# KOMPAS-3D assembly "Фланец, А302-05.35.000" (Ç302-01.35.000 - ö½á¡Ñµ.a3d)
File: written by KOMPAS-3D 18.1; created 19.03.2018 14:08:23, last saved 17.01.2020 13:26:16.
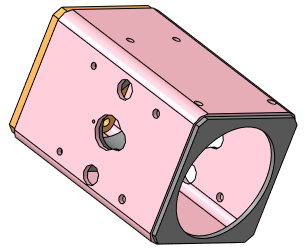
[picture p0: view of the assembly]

Document properties: Автор: Милов; Полное имя файла: D:\Мембранные насосы\Мембранный электропривод\А302-00.00.000 - ASTRA-302 (МЭ200)\3Д ПВХ\А302-01.35.000 - Фланец.a3d

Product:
- Part/product: Фланец  | designation А302-05.35.000  | pos. 0
    Масса: 15.1675
    Раздел спецификации: Сборочные единицы
    Форматы листов документа: 2xA3
    Примечание: @100~)2xA3
    source file: ..\А302-04.00.000 - Мембранный насос ASTRA-302-PP Чертежи\А302-04.35.000 - Фланец.cdw
  - Component [detail]: FB 063  | pos. 11  | Масса: 1.71461; Раздел спецификации: Детали; source file: FB 063 .m3d
  - Component [detail]: Опора подшиника  | designation А302-05.35.003  | pos. 7  | Масса: 10.2382; Раздел спецификации: Детали
  - Component [detail]: Труба 140х140х6  | designation А302-05.35.001  | pos. 1  | Масса: 2.81713; Раздел спецификации: Детали; Форматы листов документа: A4; Примечание: Заим.
  - Component [detail]: Пластина  | designation А302-05.35.002  | pos. 2  | Масса: 0.658749; Раздел спецификации: Детали; Форматы листов документа: A4; Примечание: Заим.
- Part/product: Фланец  | designation А302-04.35.000  | pos. 0
    Масса: 8.08129
    Раздел спецификации: Сборочные единицы
    Форматы листов документа: 2xA3
    Примечание: @100~)2xA3
    source file: ..\А302-04.00.000 - Мембранный насос ASTRA-302-PP Чертежи\А302-04.35.000 - Фланец.cdw, ..\А302-04.00.000 - Мембранный насос ASTRA-302-PP\А302-04.35.000 - Фланец.cdw
  - Component [detail]: Стенка  | designation А302-04.35.004  | pos. 12  | Масса: 0.256038; Раздел спецификации: Детали; source file: А302-04.35.004 - Стенка.m3d
  - Component [detail]: Пластина  | designation А302-04.35.002  | pos. 2  | Масса: 1.18936; Раздел спецификации: Детали; Форматы листов документа: A4; Примечание: Заим.
  - Component [detail]: Труба 140х140х6  | designation А302-04.35.001  | pos. 1  | Масса: 4.48359; Раздел спецификации: Детали; Форматы листов документа: A4; Примечание: Заим.
  - Component [detail]: Опора подшипника  | designation А302-04.35.003  | pos. 7  | Масса: 2.1523; Раздел спецификации: Детали; source file: А302-04.35.003 - Опора подшиника.m3d
- Part/product: Фланец  | designation А302-01.35.000  | pos. 0
    Масса: 8.26617
    Раздел спецификации: Сборочные единицы
    Форматы листов документа: 2xA3
    Примечание: @100~)2xA3
    source file: А302-01.35.000 - Фланец.cdw
  - Component [detail]: Труба 140х140х4  | designation А302-00.35.001  | pos. 1  | Масса: 4.39548; Раздел спецификации: Детали; Форматы листов документа: A4; Примечание: Заим.; source file: ..\3Д\А302-00.35.001 - Труба 140х140х4.m3d
  - Component [detail]: Пластина  | designation А302-00.35.002  | pos. 2  | Масса: 0.697075; Раздел спецификации: Детали; Форматы листов документа: A4; Примечание: Заим.; source file: ..\3Д\А302-00.35.002 - Пластина.m3d

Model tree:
1. Эскиз:1  (with: Операция выдавливания:3)
2. Вырезать элемент выдавливания:1
     Расстояние 2 = 265
3. Эскиз:2  (with: Операция выдавливания:1)
4. Вырезать элемент выдавливания:2
     Расстояние 1 = 270
5. Эскиз:3  (with: Операция выдавливания:3)
6. Вырезать элемент выдавливания:3
     Расстояние 1 = 137
7. Эскиз:4  (with: Вырезать элемент выдавливания:3)
8. Вырезать элемент выдавливания:4
     Расстояние 1 = 269
9. Эскиз:5  (with: Вырезать элемент выдавливания:3, Вырезать элемент выдавливания:4)
10. Вырезать элемент выдавливания:5
     Расстояние 1 = 10
11. Массив по концентрической сетке:1  (with: Вырезать элемент выдавливания:5, Эскиз:5, Вырезать элемент выдавливания:4)  (8 pattern instances)
     Шаг 2 = 360
12. Эскиз:6  (with: Вырезать элемент выдавливания:1, Вырезать элемент выдавливания:3)
13. Вырезать элемент выдавливания:6
     Расстояние 1 = 139.5
14. Эскиз:7  (with: Вырезать элемент выдавливания:1, Вырезать элемент выдавливания:6)
15. Вырезать элемент выдавливания:7
     Расстояние 1 = 139.5
16. Массив по концентрической сетке:2  (with: Вырезать элемент выдавливания:7, Эскиз:7, Вырезать элемент выдавливания:6)  (4 pattern instances)
     Шаг 2 = 360
17. Эскиз:8  (with: Вырезать элемент выдавливания:1, Вырезать элемент выдавливания:6, Вырезать элемент выдавливания:7)
18. Вырезать элемент выдавливания:8
     Расстояние 1 = 139.5
19. Массив по концентрической сетке:3  (with: Вырезать элемент выдавливания:8, Эскиз:8, Вырезать элемент выдавливания:6)  (2 pattern instances)
     Шаг 2 = 360
20. Эскиз:9  (with: Вырезать элемент выдавливания:2)
21. Вырезать элемент выдавливания:9
     Расстояние 1 = 7
22. Зеркальный массив:1
23. Экземпляр ( 1 )
24. Экземпляр ( 2 )  (with: Вырезать элемент выдавливания:9)
25. Эскиз:10  (with: Вырезать элемент выдавливания:1, Вырезать элемент выдавливания:6, Вырезать элемент выдавливания:7)
26. Вырезать элемент выдавливания:10
     Расстояние 1 = 139.5
27. Массив по концентрической сетке:4  (with: Вырезать элемент выдавливания:10, Эскиз:10, Вырезать элемент выдавливания:6)  (3 pattern instances)
     Шаг 2 = 180
28. Эскиз:11  (with: Операция выдавливания:1)
29. Вырезать элемент выдавливания:11
     Расстояние 1 = 10; На расстояние 1 = 8
30. Зеркальный массив:2  (with: Экземпляр ( 1 ), Экземпляр ( 2 ), Вырезать элемент выдавливания:11)
31. Эскиз:12  (with: Вырезать элемент выдавливания:1, Вырезать элемент выдавливания:6)
32. Вырезать элемент выдавливания:12
     Расстояние 1 = 139.5; На расстояние 1 = 8
33. Условное изображение резьбы:1  (with: Вырезать элемент выдавливания:12)  (labels: M4; cil0_24705-2004 coarse)
     Длина резьбы = 3.5; Шаг резьбы = 0.7; Номинальный диаметр резьбы = 4
34. Подгонка:1  (with: Вырезать элемент выдавливания:12)
35. Условное изображение резьбы:2  (with: Вырезать элемент выдавливания:12)  (labels: M4; cil0_24705-2004 coarse)
     Длина резьбы = 3.5; Шаг резьбы = 0.7; Номинальный диаметр резьбы = 4
36. Подгонка:2  (with: Вырезать элемент выдавливания:12)
37. Фаска:1  (with: Вырезать элемент выдавливания:12)
     Угол = 45; Длина 1 = 0.5; Длина 2 = 0.5
38. Эскиз:13  (with: Вырезать элемент выдавливания:2, Вырезать элемент выдавливания:11)
39. Элемент выдавливания:1  (with: Операция выдавливания:3, Операция выдавливания:1)
     Расстояние 2 = 10
40. Эскиз:14  (with: Операция выдавливания:1)
41. Элемент выдавливания:3
     Расстояние 1 = 133.5; Расстояние 2 = 5.5
42. Условное изображение резьбы:3  (with: Элемент выдавливания:3, Элемент выдавливания:12)  (labels: M8x1; cil0_24705-2004 fine)
     Длина резьбы = 10; Шаг резьбы = 1; Номинальный диаметр резьбы = 8
43. Подгонка:1  (with: Элемент выдавливания:3)
44. Условное изображение резьбы:4  (with: Элемент выдавливания:3, Элемент выдавливания:12)  (labels: M8x1; cil0_24705-2004 fine)
     Длина резьбы = 10; Шаг резьбы = 1; Номинальный диаметр резьбы = 8
45. Подгонка:2  (with: Элемент выдавливания:3)
46. Условное изображение резьбы:5  (with: Элемент выдавливания:3, Элемент выдавливания:12)  (labels: M8x1; cil0_24705-2004 fine)
     Длина резьбы = 10; Шаг резьбы = 1; Номинальный диаметр резьбы = 8
47. Подгонка:3  (with: Элемент выдавливания:3)
48. Условное изображение резьбы:6  (with: Элемент выдавливания:3, Элемент выдавливания:12)  (labels: M8x1; cil0_24705-2004 fine)
     Длина резьбы = 10; Шаг резьбы = 1; Номинальный диаметр резьбы = 8
49. Подгонка:4  (with: Элемент выдавливания:3)
50. Отверстие:6  (with: Элемент выдавливания:2)  (labels: M8x1)
     Глубина выреза = 30; Диаметр отверстия = 6.91747; Угол конуса дна = 118; Расстояние 1 = 107; Расстояние 2 = 64
51. M8x1  (with: Отверстие:6, Элемент выдавливания:2)  (labels: M8x1; cil0_24705-2004 fine)
     Длина резьбы = 20; Шаг резьбы = 1; Номинальный диаметр резьбы = 8
52. Отверстие:7  (with: Элемент выдавливания:2, M8x1)  (labels: M8x1; cil0_24705-2004 fine)
     Глубина выреза = 30; Диаметр отверстия = 6.91747; Угол конуса дна = 118; Расстояние 1 = 15; Расстояние 2 = 64; Длина резьбы = 20; Шаг резьбы = 1; Номинальный диаметр резьбы = 8
53. Зеркальный массив:3
54. Экземпляр ( 1 )
55. Экземпляр ( 2 )  (with: Отверстие:7)
56. Отверстие:6
57. Эскиз:16  (with: Операция выдавливания:1)
58. Элемент выдавливания:7
     Расстояние 1 = 10
59. Элемент выдавливания:8  (with: Элемент выдавливания:1)
     Расстояние 2 = 3
60. Точка:1  (with: Элемент выдавливания:7)
     X = 31.5; Y = -70; Z = 129.5
61. Точка:2  (with: Элемент выдавливания:7)
     X = -31.5; Y = -70; Z = 129.5
62. Отверстие:8  (with: Элемент выдавливания:1, Фаска:1, M8x1)  (labels: M8x1; cil0_24705-2004 fine)
     Глубина выреза = 15; Диаметр отверстия = 6.91747; Угол конуса дна = 118; Расстояние 1 = -85.5; Расстояние 2 = 12.5; Длина резьбы = 15; Шаг резьбы = 1; Номинальный диаметр резьбы = 8
63. Отверстие:9  (with: Элемент выдавливания:1, Фаска:1, M8x1, Операция выдавливания:3, Элемент выдавливания:8)  (labels: M8x1; cil0_24705-2004 fine)
     Глубина выреза = 15; Диаметр отверстия = 6.91747; Угол конуса дна = 118; Расстояние 1 = -22.5; Расстояние 2 = 12.5; Длина резьбы = 15; Шаг резьбы = 1; Номинальный диаметр резьбы = 8; Расстояние = 50; Ориентация = 2

Referenced files in D:\Мембранные насосы\Мембранный электропривод\А302-00.00.000 - ASTRA-302 (МЭ200)\3Д\: А302-00.35.002 - Пластина.m3d, А302-00.35.001 - Труба 140х140х4.m3d
Referenced files in D:\Мембранные насосы\Мембранный электропривод\А302-00.00.000 - ASTRA-302 (МЭ200)\3Д ПВХ\: А302-04.35.003 - Опора подшиника.m3d, FB 063 .m3d, А302-04.35.004 - Стенка.m3d, А302-01.35.000 - Фланец.cdw
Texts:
  @100~)2xA3
  Точка начала. Х
  Точка начала. Y
  Точка начала. Z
